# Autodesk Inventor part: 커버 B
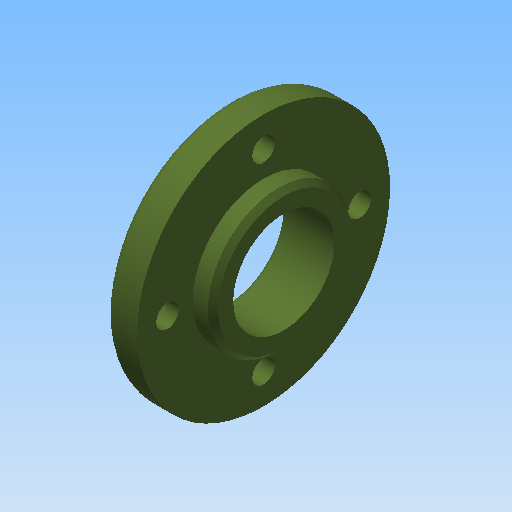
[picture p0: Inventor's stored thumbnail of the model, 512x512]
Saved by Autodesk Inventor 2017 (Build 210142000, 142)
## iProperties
Created: 2019-01
Part Number: 커버 B
Material: 알루미늄 6061
Document SubType Name: Modeling
Designer: mduedu
Density: 2.71 g/cm^3
Appearance: 올리브 녹색
Mass: 30.6342 g
Surface Area: 56.1508 cm^2
Volume: 11.3041 cm^3
Author: mduedu
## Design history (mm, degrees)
sketch "스케치1"
  geometry: L1 (0, 0)-(7, 0); L2 (7, 0)-(7, 25); L3 (7, 25)-(0, 25); L4 (0, 25)-(0, 0); L5 (7, 0)-(11, 0); L6 (11, 0)-(11, 14); L7 (11, 14)-(7, 14); L8 (7, 14)-(7, 0)
  constraints: 16 end point, 4 parallel, 2 horizontal, 2 perpendicular
  dimensions: "d0" = 50 diameter of L3 L1; "d2" = 11 distance between parallel lines of L6 L4; "d3" = 7 distance of L2.end L3.end; "d4" = 28 diameter of L7 L5
revolve "회전1" sketch "스케치1" stored, may be unused: angle "d5" = 90 deg
sketch "스케치2"
  geometry: C1 r 10 at (0, 0); 1 further point
  constraints: 1 centre point, 1 coincident
  dimensions: "d6" = 20 diameter of C1
extrude "돌출1" cut sketch "스케치2" stored distance "d7" = 10; taper "d8" = 0 deg
chamfer "모따기1" distance "d9" = 1; stored, may be unused: second distance "d10" = 2, angle "d11" = 45 deg
fillet "모깎기1" dims "d12" = 3
sketch "스케치3" dims "d13" = 38
  geometry: 6 further points
  constraints: 2 vertical alignment, 1 coincident, 7 other
  dimensions: "d16" = 360 deg dimension on point (0, 0) point (0, 19) (derived)
chamfer "모따기2" distance "d18" = 1; stored, may be unused: second distance "d19" = 2, angle "d20" = 45 deg
sketch "스케치4"
  geometry: 4 further points
  constraints: 4 other
hole "구멍1" sketch "스케치4" at (-19, 0), (0, -19), (19, 0), (0, 19) diameter "d21" = 4.5; stored, may be unused: countersink angle "d25" = 90 deg, drill point angle "d27" = 0 deg; dims "d22" = 6, "d23" = 8, "d24" = 4.6, "d26" = 8
node "솔리드1"
